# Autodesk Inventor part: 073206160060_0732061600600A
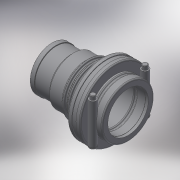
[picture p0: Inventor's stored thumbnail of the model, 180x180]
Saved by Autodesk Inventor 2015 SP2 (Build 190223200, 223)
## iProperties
Created: 2017-05
Part Number: 073206160060_0732061600600A
Material: Generic
Description: PLASSON SHOULDERED ADAPTOR 160-6"
Document SubType Name: Modeling
Designer: Кирилл
Density: 1 g/cm^3
Appearance: Default
Author: Кирилл
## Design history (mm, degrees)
derived "073206.ipt"
feature "Solid1::073206.ipt"
tag "TaggingFeature1"
body "Solid1"
other parameters: "d0" = 304, "d3" = 208, "d4" = 192, "d5" = 4.8, "d6" = 51, "d7" = 274.4, "d9" = 204, "d10" = 51, "d11" = 9.6, "d12" = 51, "d13" = 10.2, "d15" = 4.8, "d17" = 161.6, "d18" = 11.55, "d19" = 0, "d21" = 0, "d23" = 20.16, "d24" = 16, "d25" = 0, "d26" = 1.6, "d29" = 0.1, "d30" = 8, "d31" = 0, "d32" = 4.8, "d40" = 175, "d41" = 135 deg, "d42" = 18, "d46" = 76, "d68" = 0.875, "d77" = 169.75, "l_" = 204, "H_" = 304, "B_" = 175, "L_" = 18, "d16" = 46.2, "d22" = 28.8
